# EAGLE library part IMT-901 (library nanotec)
Schrittmotor / Mikroschritt-PWM-Konstantstrom-Treiber Source: http://de.nanotec.com .. s094-095_leistungsendst_IMT901.pdf
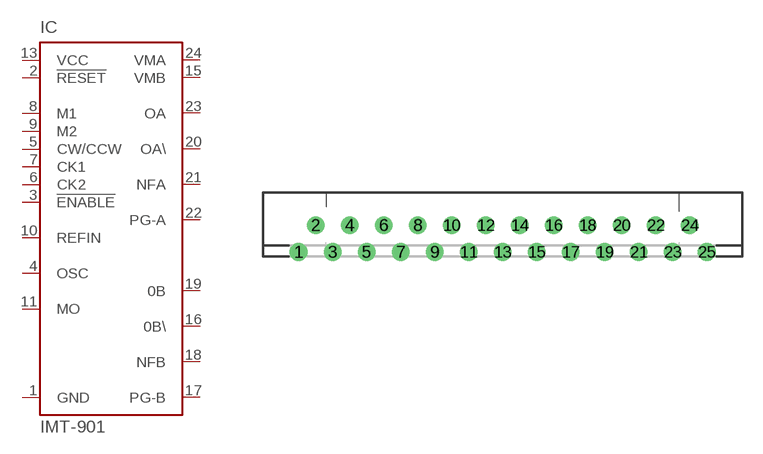
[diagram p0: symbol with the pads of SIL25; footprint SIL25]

Designator prefix IC

## IMT-901 (MPN: IMT-901; OC_FARNELL: 4743295; OC_NEWARK: 17M9708)  [SIL25]
1  GND  pwr
2  !RESET  in
3  !ENABLE  in
4  OSC  in
5  CW/CCW  in
6  CK2  in
7  CK1  in
8  M1  in
9  M2  in
10  REFIN  in
11  MO  in
12  NC  nc
13  VCC  pwr
14  NC  nc
15  VMB  in
16  0B\\  out
17  PG-B  in
18  NFB  in
19  0B  out
20  OA\\  out
21  NFA  in
22  PG-A  in
23  OA  out
24  VMA  in
25  NC  nc

## Footprint SIL25 (pad centres in mm)
Single In Line 25 Grid 1.27mm Source: http://de.nanotec.com .. s094-095_leistungsendst_IMT901.pdf
drill 0.8 pad 1.3 round: 1 -15.24,-2; 2 -13.97,0; 3 -12.7,-2; 4 -11.43,0; 5 -10.16,-2; 6 -8.89,0; 7 -7.62,-2; 8 -6.35,0; 9 -5.08,-2; 10 -3.81,0; 11 -2.54,-2; 12 -1.27,0; 13 0,-2; 14 1.27,0; 15 2.54,-2; 16 3.81,0; 17 5.08,-2; 18 6.35,0; 19 7.62,-2; 20 8.89,0; 21 10.16,-2; 22 11.43,0; 23 12.7,-2; 24 13.97,0; 25 15.24,-2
